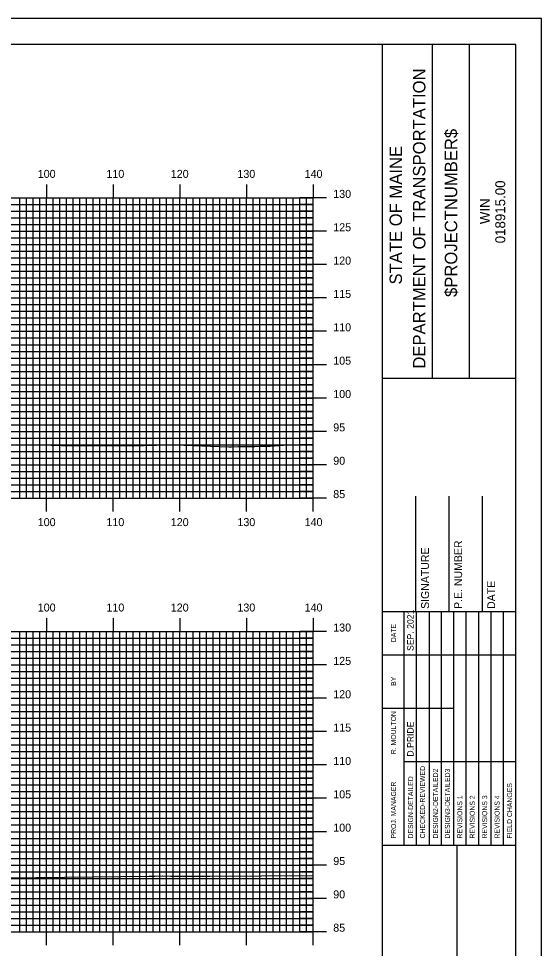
# Model space of a CAD drawing. Extents: x 1785795 to 1786139, y 442591 to 442811.
# Drawn here: x 1786056.9 to 1786135.3, y 442671.2 to 442810.5 of the extents above; entities that cross this region are included whole.
import ezdxf

# ---------------------------------------------------------------- set-up
doc = ezdxf.new("R2010")
doc.units = 0
for name, color, linetype in [('BORDER', 7, 'Continuous'), ('H_V ANNOTATION', 7, 'Continuous'), ('MAJOR', 7, 'Continuous'), ('MINOR', 7, 'Continuous'), ('PLOT BOUNDARY', 7, 'Continuous'), ('S_Roadway_Centerline', 7, 'Continuous')]:
    doc.layers.add(name, color=color, linetype=linetype)

msp = doc.modelspace()

# ---------------------------------------------------------------- linework, layer by layer
at = {"layer": 'BORDER'}
for p, q in [((1786111.45, 442596.67), (1786111.45, 442806.67)), ((1786118.91, 442756.66), (1786118.91, 442806.66)), ((1786124.5, 442756.66), (1786124.5, 442806.66)), ((1786111.45, 442756.65), (1786131.45, 442756.65)), ((1786116.45, 442721.67), (1786116.45, 442738.97)), ((1786121.45, 442721.67), (1786121.45, 442738.97)), ((1786126.45, 442721.67), (1786126.45, 442738.97)), ((1786111.45, 442721.67), (1786131.45, 442721.67)), ((1786111.45, 442686.67), (1786131.45, 442686.67)), ((1786122.63, 442616.67), (1786122.63, 442686.67))]:
    msp.add_line(p, q, dxfattribs=at)
msp.add_lwpolyline([(1785811.45, 442596.67), (1786131.45, 442596.67), (1786131.45, 442806.67), (1785811.45, 442806.67)], close=True, dxfattribs=at)
for points in [[(1786114.68, 442715.17), (1786114.68, 442721.67)], [(1786116.55, 442686.68), (1786116.55, 442721.67)], [(1786118.41, 442721.67), (1786118.41, 442686.68)], [(1786120.27, 442686.68), (1786120.27, 442721.67)], [(1786122.14, 442686.68), (1786122.14, 442721.67)], [(1786124, 442686.68), (1786124, 442721.67)], [(1786125.86, 442686.68), (1786125.86, 442721.67)], [(1786127.73, 442686.68), (1786127.73, 442721.67)], [(1786129.59, 442686.68), (1786129.59, 442721.67)], [(1786114.68, 442686.68), (1786114.68, 442720.26)], [(1786111.45, 442715.17), (1786131.45, 442715.17)], [(1786111.45, 442707.17), (1786114.68, 442707.17)], [(1786114.68, 442707.17), (1786122.13, 442707.17)], [(1786114.68, 442699.17), (1786131.45, 442699.17)]]:
    msp.add_lwpolyline(points, dxfattribs=at)
at = {"layer": 'MAJOR'}
for p, q in [((1786061.05, 442785.67), (1786061.05, 442783.67)), ((1786071.05, 442785.67), (1786071.05, 442783.67)), ((1786081.05, 442785.67), (1786081.05, 442783.67)), ((1786091.05, 442785.67), (1786091.05, 442783.67)), ((1786101.05, 442785.67), (1786101.05, 442783.67)), ((1785821.05, 442783.67), (1786101.05, 442783.67)), ((1785821.05, 442783.67), (1786101.05, 442783.67)), ((1786061.05, 442738.67), (1786061.05, 442783.67)), ((1786071.05, 442738.67), (1786071.05, 442783.67)), ((1786081.05, 442738.67), (1786081.05, 442783.67)), ((1786091.05, 442738.67), (1786091.05, 442783.67)), ((1786103.06, 442783.67), (1786099.05, 442783.67)), ((1786101.05, 442738.67), (1786101.05, 442783.67)), ((1786101.05, 442738.67), (1786101.05, 442783.67)), ((1785821.05, 442778.67), (1786101.05, 442778.67)), ((1786103.06, 442778.67), (1786099.05, 442778.67)), ((1785821.05, 442773.67), (1786101.05, 442773.67)), ((1786103.06, 442773.67), (1786099.05, 442773.67)), ((1785821.05, 442768.67), (1786101.05, 442768.67)), ((1786103.06, 442768.67), (1786099.05, 442768.67)), ((1785821.05, 442763.67), (1786101.05, 442763.67)), ((1786103.06, 442763.67), (1786099.05, 442763.67)), ((1785821.05, 442758.67), (1786101.05, 442758.67)), ((1786103.06, 442758.67), (1786099.05, 442758.67)), ((1785821.05, 442753.67), (1786101.05, 442753.67)), ((1786103.06, 442753.67), (1786099.05, 442753.67)), ((1785821.05, 442748.67), (1786101.05, 442748.67)), ((1786103.06, 442748.67), (1786099.05, 442748.67)), ((1785821.05, 442743.67), (1786101.05, 442743.67)), ((1786103.06, 442743.67), (1786099.05, 442743.67)), ((1785821.05, 442738.67), (1786101.05, 442738.67)), ((1785821.05, 442738.67), (1786101.05, 442738.67)), ((1786061.05, 442736.66), (1786061.05, 442738.67)), ((1786071.05, 442736.66), (1786071.05, 442738.67)), ((1786081.05, 442736.66), (1786081.05, 442738.67)), ((1786091.05, 442736.66), (1786091.05, 442738.67)), ((1786103.06, 442738.67), (1786099.05, 442738.67)), ((1786101.05, 442736.66), (1786101.05, 442738.67)), ((1786061.05, 442720.67), (1786061.05, 442718.67)), ((1786071.05, 442720.67), (1786071.05, 442718.67)), ((1786081.05, 442720.67), (1786081.05, 442718.67)), ((1786091.05, 442720.67), (1786091.05, 442718.67)), ((1786101.05, 442720.67), (1786101.05, 442718.67)), ((1785821.05, 442718.67), (1786101.05, 442718.67)), ((1785821.05, 442718.67), (1786101.05, 442718.67)), ((1786061.05, 442673.67), (1786061.05, 442718.67)), ((1786071.05, 442673.67), (1786071.05, 442718.67)), ((1786081.05, 442673.67), (1786081.05, 442718.67)), ((1786091.05, 442673.67), (1786091.05, 442718.67)), ((1786103.06, 442718.67), (1786099.05, 442718.67)), ((1786101.05, 442673.67), (1786101.05, 442718.67)), ((1786101.05, 442673.67), (1786101.05, 442718.67)), ((1785821.05, 442713.67), (1786101.05, 442713.67)), ((1786103.06, 442713.67), (1786099.05, 442713.67)), ((1785821.05, 442708.67), (1786101.05, 442708.67)), ((1786103.06, 442708.67), (1786099.05, 442708.67)), ((1785821.05, 442703.67), (1786101.05, 442703.67)), ((1786103.06, 442703.67), (1786099.05, 442703.67)), ((1785821.05, 442698.67), (1786101.05, 442698.67)), ((1786103.06, 442698.67), (1786099.05, 442698.67)), ((1785821.05, 442693.67), (1786101.05, 442693.67)), ((1786103.06, 442693.67), (1786099.05, 442693.67)), ((1785821.05, 442688.67), (1786101.05, 442688.67)), ((1786103.06, 442688.67), (1786099.05, 442688.67)), ((1785821.05, 442683.67), (1786101.05, 442683.67)), ((1786103.06, 442683.67), (1786099.05, 442683.67)), ((1785821.05, 442678.67), (1786101.05, 442678.67)), ((1786103.06, 442678.67), (1786099.05, 442678.67)), ((1785821.05, 442673.67), (1786101.05, 442673.67)), ((1785821.05, 442673.67), (1786101.05, 442673.67)), ((1786061.05, 442671.66), (1786061.05, 442673.67)), ((1786071.05, 442671.66), (1786071.05, 442673.67)), ((1786081.05, 442671.66), (1786081.05, 442673.67)), ((1786091.05, 442671.66), (1786091.05, 442673.67)), ((1786103.06, 442673.67), (1786099.05, 442673.67)), ((1786101.05, 442671.66), (1786101.05, 442673.67))]:
    msp.add_line(p, q, dxfattribs=at)
at = {"layer": 'MINOR'}
for p, q in [((1785821.05, 442782.67), (1786101.05, 442782.67)), ((1786057.05, 442738.67), (1786057.05, 442783.67)), ((1786058.05, 442738.67), (1786058.05, 442783.67)), ((1786059.05, 442738.67), (1786059.05, 442783.67)), ((1786060.05, 442738.67), (1786060.05, 442783.67)), ((1786062.05, 442738.67), (1786062.05, 442783.67)), ((1786063.05, 442738.67), (1786063.05, 442783.67)), ((1786064.05, 442738.67), (1786064.05, 442783.67)), ((1786065.05, 442738.67), (1786065.05, 442783.67)), ((1786066.05, 442738.67), (1786066.05, 442783.67)), ((1786067.05, 442738.67), (1786067.05, 442783.67)), ((1786068.05, 442738.67), (1786068.05, 442783.67)), ((1786069.05, 442738.67), (1786069.05, 442783.67)), ((1786070.05, 442738.67), (1786070.05, 442783.67)), ((1786072.05, 442738.67), (1786072.05, 442783.67)), ((1786073.05, 442738.67), (1786073.05, 442783.67)), ((1786074.05, 442738.67), (1786074.05, 442783.67)), ((1786075.05, 442738.67), (1786075.05, 442783.67)), ((1786076.05, 442738.67), (1786076.05, 442783.67)), ((1786077.05, 442738.67), (1786077.05, 442783.67)), ((1786078.05, 442738.67), (1786078.05, 442783.67)), ((1786079.05, 442738.67), (1786079.05, 442783.67)), ((1786080.05, 442738.67), (1786080.05, 442783.67)), ((1786082.05, 442738.67), (1786082.05, 442783.67)), ((1786083.05, 442738.67), (1786083.05, 442783.67)), ((1786084.05, 442738.67), (1786084.05, 442783.67)), ((1786085.05, 442738.67), (1786085.05, 442783.67)), ((1786086.05, 442738.67), (1786086.05, 442783.67)), ((1786087.05, 442738.67), (1786087.05, 442783.67)), ((1786088.05, 442738.67), (1786088.05, 442783.67)), ((1786089.05, 442738.67), (1786089.05, 442783.67)), ((1786090.05, 442738.67), (1786090.05, 442783.67)), ((1786092.05, 442738.67), (1786092.05, 442783.67)), ((1786093.05, 442738.67), (1786093.05, 442783.67)), ((1786094.05, 442738.67), (1786094.05, 442783.67)), ((1786095.05, 442738.67), (1786095.05, 442783.67)), ((1786096.05, 442738.67), (1786096.05, 442783.67)), ((1786097.05, 442738.67), (1786097.05, 442783.67)), ((1786098.05, 442738.67), (1786098.05, 442783.67)), ((1786099.05, 442738.67), (1786099.05, 442783.67)), ((1786101.05, 442782.67), (1786099.05, 442782.67)), ((1786100.05, 442738.67), (1786100.05, 442783.67)), ((1785821.05, 442781.67), (1786101.05, 442781.67)), ((1786101.05, 442781.67), (1786099.05, 442781.67)), ((1785821.05, 442780.67), (1786101.05, 442780.67)), ((1786101.05, 442780.67), (1786099.05, 442780.67)), ((1785821.05, 442779.67), (1786101.05, 442779.67)), ((1786101.05, 442779.67), (1786099.05, 442779.67)), ((1785821.05, 442777.67), (1786101.05, 442777.67)), ((1786101.05, 442777.67), (1786099.05, 442777.67)), ((1785821.05, 442776.67), (1786101.05, 442776.67)), ((1785821.05, 442775.67), (1786101.05, 442775.67)), ((1786101.05, 442776.67), (1786099.05, 442776.67)), ((1786101.05, 442775.67), (1786099.05, 442775.67)), ((1785821.05, 442774.67), (1786101.05, 442774.67)), ((1786101.05, 442774.67), (1786099.05, 442774.67)), ((1785821.05, 442772.67), (1786101.05, 442772.67)), ((1785821.05, 442771.67), (1786101.05, 442771.67)), ((1786101.05, 442772.67), (1786099.05, 442772.67)), ((1786101.05, 442771.67), (1786099.05, 442771.67)), ((1785821.05, 442770.67), (1786101.05, 442770.67)), ((1786101.05, 442770.67), (1786099.05, 442770.67)), ((1785821.05, 442769.67), (1786101.05, 442769.67)), ((1786101.05, 442769.67), (1786099.05, 442769.67)), ((1785821.05, 442767.67), (1786101.05, 442767.67)), ((1786101.05, 442767.67), (1786099.05, 442767.67)), ((1785821.05, 442766.67), (1786101.05, 442766.67)), ((1786101.05, 442766.67), (1786099.05, 442766.67)), ((1785821.05, 442765.67), (1786101.05, 442765.67)), ((1785821.05, 442764.67), (1786101.05, 442764.67)), ((1786101.05, 442765.67), (1786099.05, 442765.67)), ((1786101.05, 442764.67), (1786099.05, 442764.67)), ((1785821.05, 442762.67), (1786101.05, 442762.67)), ((1785821.05, 442761.67), (1786101.05, 442761.67)), ((1786101.05, 442762.67), (1786099.05, 442762.67)), ((1786101.05, 442761.67), (1786099.05, 442761.67)), ((1785821.05, 442760.67), (1786101.05, 442760.67)), ((1786101.05, 442760.67), (1786099.05, 442760.67)), ((1785821.05, 442759.67), (1786101.05, 442759.67)), ((1786101.05, 442759.67), (1786099.05, 442759.67)), ((1785821.05, 442757.67), (1786101.05, 442757.67)), ((1786101.05, 442757.67), (1786099.05, 442757.67)), ((1785821.05, 442756.67), (1786101.05, 442756.67)), ((1786101.05, 442756.67), (1786099.05, 442756.67)), ((1785821.05, 442755.67), (1786101.05, 442755.67)), ((1785821.05, 442754.67), (1786101.05, 442754.67)), ((1786101.05, 442755.67), (1786099.05, 442755.67)), ((1786101.05, 442754.67), (1786099.05, 442754.67)), ((1785821.05, 442752.67), (1786101.05, 442752.67)), ((1786101.05, 442752.67), (1786099.05, 442752.67)), ((1785821.05, 442751.67), (1786101.05, 442751.67)), ((1785821.05, 442750.67), (1786101.05, 442750.67)), ((1786101.05, 442751.67), (1786099.05, 442751.67)), ((1786101.05, 442750.67), (1786099.05, 442750.67)), ((1785821.05, 442749.67), (1786101.05, 442749.67)), ((1786101.05, 442749.67), (1786099.05, 442749.67)), ((1785821.05, 442747.67), (1786101.05, 442747.67)), ((1786101.05, 442747.67), (1786099.05, 442747.67)), ((1785821.05, 442746.67), (1786101.05, 442746.67)), ((1786101.05, 442746.67), (1786099.05, 442746.67)), ((1785821.05, 442745.67), (1786101.05, 442745.67)), ((1786101.05, 442745.67), (1786099.05, 442745.67)), ((1785821.05, 442744.67), (1786101.05, 442744.67)), ((1786101.05, 442744.67), (1786099.05, 442744.67)), ((1785821.05, 442742.67), (1786101.05, 442742.67)), ((1786101.05, 442742.67), (1786099.05, 442742.67)), ((1785821.05, 442741.67), (1786101.05, 442741.67)), ((1786101.05, 442741.67), (1786099.05, 442741.67)), ((1785821.05, 442740.67), (1786101.05, 442740.67)), ((1785821.05, 442739.67), (1786101.05, 442739.67)), ((1786101.05, 442740.67), (1786099.05, 442740.67)), ((1786101.05, 442739.67), (1786099.05, 442739.67)), ((1786057.05, 442673.67), (1786057.05, 442718.67)), ((1786058.05, 442673.67), (1786058.05, 442718.67)), ((1786059.05, 442673.67), (1786059.05, 442718.67)), ((1786060.05, 442673.67), (1786060.05, 442718.67)), ((1786062.05, 442673.67), (1786062.05, 442718.67)), ((1786063.05, 442673.67), (1786063.05, 442718.67)), ((1786064.05, 442673.67), (1786064.05, 442718.67)), ((1786065.05, 442673.67), (1786065.05, 442718.67)), ((1786066.05, 442673.67), (1786066.05, 442718.67)), ((1786067.05, 442673.67), (1786067.05, 442718.67)), ((1786068.05, 442673.67), (1786068.05, 442718.67)), ((1786069.05, 442673.67), (1786069.05, 442718.67)), ((1786070.05, 442673.67), (1786070.05, 442718.67)), ((1786072.05, 442673.67), (1786072.05, 442718.67)), ((1786073.05, 442673.67), (1786073.05, 442718.67)), ((1786074.05, 442673.67), (1786074.05, 442718.67)), ((1786075.05, 442673.67), (1786075.05, 442718.67)), ((1786076.05, 442673.67), (1786076.05, 442718.67)), ((1786077.05, 442673.67), (1786077.05, 442718.67)), ((1786078.05, 442673.67), (1786078.05, 442718.67)), ((1786079.05, 442673.67), (1786079.05, 442718.67)), ((1786080.05, 442673.67), (1786080.05, 442718.67)), ((1786082.05, 442673.67), (1786082.05, 442718.67)), ((1786083.05, 442673.67), (1786083.05, 442718.67)), ((1786084.05, 442673.67), (1786084.05, 442718.67)), ((1786085.05, 442673.67), (1786085.05, 442718.67)), ((1786086.05, 442673.67), (1786086.05, 442718.67)), ((1786087.05, 442673.67), (1786087.05, 442718.67)), ((1786088.05, 442673.67), (1786088.05, 442718.67)), ((1786089.05, 442673.67), (1786089.05, 442718.67)), ((1786090.05, 442673.67), (1786090.05, 442718.67)), ((1786092.05, 442673.67), (1786092.05, 442718.67)), ((1786093.05, 442673.67), (1786093.05, 442718.67)), ((1786094.05, 442673.67), (1786094.05, 442718.67)), ((1786095.05, 442673.67), (1786095.05, 442718.67)), ((1786096.05, 442673.67), (1786096.05, 442718.67)), ((1786097.05, 442673.67), (1786097.05, 442718.67)), ((1786098.05, 442673.67), (1786098.05, 442718.67)), ((1786099.05, 442673.67), (1786099.05, 442718.67)), ((1786100.05, 442673.67), (1786100.05, 442718.67)), ((1785821.05, 442717.67), (1786101.05, 442717.67)), ((1786101.05, 442717.67), (1786099.05, 442717.67)), ((1785821.05, 442716.67), (1786101.05, 442716.67)), ((1785821.05, 442715.67), (1786101.05, 442715.67)), ((1786101.05, 442716.67), (1786099.05, 442716.67)), ((1786101.05, 442715.67), (1786099.05, 442715.67)), ((1785821.05, 442714.67), (1786101.05, 442714.67)), ((1786101.05, 442714.67), (1786099.05, 442714.67)), ((1785821.05, 442712.67), (1786101.05, 442712.67)), ((1785821.05, 442711.67), (1786101.05, 442711.67)), ((1786101.05, 442712.67), (1786099.05, 442712.67)), ((1786101.05, 442711.67), (1786099.05, 442711.67)), ((1785821.05, 442710.67), (1786101.05, 442710.67)), ((1786101.05, 442710.67), (1786099.05, 442710.67)), ((1785821.05, 442709.67), (1786101.05, 442709.67)), ((1786101.05, 442709.67), (1786099.05, 442709.67)), ((1785821.05, 442707.67), (1786101.05, 442707.67)), ((1786101.05, 442707.67), (1786099.05, 442707.67)), ((1785821.05, 442706.67), (1786101.05, 442706.67)), ((1786101.05, 442706.67), (1786099.05, 442706.67)), ((1785821.05, 442705.67), (1786101.05, 442705.67)), ((1785821.05, 442704.67), (1786101.05, 442704.67)), ((1786101.05, 442705.67), (1786099.05, 442705.67)), ((1786101.05, 442704.67), (1786099.05, 442704.67)), ((1785821.05, 442702.67), (1786101.05, 442702.67)), ((1785821.05, 442701.67), (1786101.05, 442701.67)), ((1786101.05, 442702.67), (1786099.05, 442702.67)), ((1786101.05, 442701.67), (1786099.05, 442701.67)), ((1785821.05, 442700.67), (1786101.05, 442700.67)), ((1786101.05, 442700.67), (1786099.05, 442700.67)), ((1785821.05, 442699.67), (1786101.05, 442699.67)), ((1786101.05, 442699.67), (1786099.05, 442699.67)), ((1785821.05, 442697.67), (1786101.05, 442697.67)), ((1786101.05, 442697.67), (1786099.05, 442697.67)), ((1785821.05, 442696.67), (1786101.05, 442696.67)), ((1786101.05, 442696.67), (1786099.05, 442696.67)), ((1785821.05, 442695.67), (1786101.05, 442695.67)), ((1786101.05, 442695.67), (1786099.05, 442695.67)), ((1785821.05, 442694.67), (1786101.05, 442694.67)), ((1786101.05, 442694.67), (1786099.05, 442694.67)), ((1785821.05, 442692.67), (1786101.05, 442692.67)), ((1786101.05, 442692.67), (1786099.05, 442692.67)), ((1785821.05, 442691.67), (1786101.05, 442691.67)), ((1785821.05, 442690.67), (1786101.05, 442690.67)), ((1786101.05, 442691.67), (1786099.05, 442691.67)), ((1786101.05, 442690.67), (1786099.05, 442690.67)), ((1785821.05, 442689.67), (1786101.05, 442689.67)), ((1786101.05, 442689.67), (1786099.05, 442689.67)), ((1785821.05, 442687.67), (1786101.05, 442687.67)), ((1785821.05, 442686.67), (1786101.05, 442686.67)), ((1786101.05, 442687.67), (1786099.05, 442687.67)), ((1786101.05, 442686.67), (1786099.05, 442686.67)), ((1785821.05, 442685.67), (1786101.05, 442685.67)), ((1786101.05, 442685.67), (1786099.05, 442685.67)), ((1785821.05, 442684.67), (1786101.05, 442684.67)), ((1786101.05, 442684.67), (1786099.05, 442684.67)), ((1785821.05, 442682.67), (1786101.05, 442682.67)), ((1786101.05, 442682.67), (1786099.05, 442682.67)), ((1785821.05, 442681.67), (1786101.05, 442681.67)), ((1786101.05, 442681.67), (1786099.05, 442681.67)), ((1785821.05, 442680.67), (1786101.05, 442680.67)), ((1785821.05, 442679.67), (1786101.05, 442679.67)), ((1786101.05, 442680.67), (1786099.05, 442680.67)), ((1786101.05, 442679.67), (1786099.05, 442679.67)), ((1785821.05, 442677.67), (1786101.05, 442677.67)), ((1785821.05, 442676.67), (1786101.05, 442676.67)), ((1786101.05, 442677.67), (1786099.05, 442677.67)), ((1786101.05, 442676.67), (1786099.05, 442676.67)), ((1785821.05, 442675.67), (1786101.05, 442675.67)), ((1786101.05, 442675.67), (1786099.05, 442675.67)), ((1785821.05, 442674.67), (1786101.05, 442674.67)), ((1786101.05, 442674.67), (1786099.05, 442674.67))]:
    msp.add_line(p, q, dxfattribs=at)
at = {"layer": 'PLOT BOUNDARY'}
msp.add_lwpolyline([(1785795.27, 442590.55), (1786135.27, 442590.55), (1786135.27, 442810.55), (1785795.27, 442810.55)], close=True, dxfattribs=at)
at = {"layer": 'S_Roadway_Centerline'}
for points in [[(1786056.62, 442746.7), (1786061.74, 442746.62), (1786062.58, 442746.59), (1786063.29, 442746.57), (1786063.83, 442746.56), (1786065.2, 442746.55), (1786066.05, 442746.56), (1786066.5, 442746.56), (1786066.94, 442746.57), (1786067.36, 442746.57), (1786067.72, 442746.57), (1786068.03, 442746.58), (1786069.03, 442746.58), (1786069.39, 442746.58), (1786073.88, 442746.52), (1786079.37, 442746.66), (1786079.37, 442746.66), (1786079.38, 442746.66), (1786079.39, 442746.66), (1786079.4, 442746.66), (1786079.42, 442746.66), (1786079.43, 442746.66), (1786079.45, 442746.66), (1786079.47, 442746.66), (1786079.52, 442746.66), (1786079.56, 442746.66), (1786079.59, 442746.66), (1786079.63, 442746.66), (1786079.64, 442746.66), (1786079.67, 442746.66), (1786079.71, 442746.66), (1786079.73, 442746.66), (1786079.75, 442746.66), (1786079.77, 442746.66), (1786079.79, 442746.66), (1786079.81, 442746.65), (1786079.85, 442746.65), (1786079.95, 442746.65), (1786080.01, 442746.65), (1786080.08, 442746.65), (1786080.17, 442746.64), (1786080.29, 442746.64), (1786088.37, 442746.38), (1786088.55, 442746.37), (1786088.56, 442746.37), (1786088.59, 442746.37), (1786088.81, 442746.37), (1786089.79, 442746.39), (1786090.7, 442746.4), (1786091.54, 442746.42), (1786092.31, 442746.43), (1786092.99, 442746.45), (1786094.12, 442746.47), (1786094.58, 442746.48), (1786097.96, 442746.69), (1786101.05, 442746.65)], [(1786054.76, 442681.74), (1786059.54, 442681.8), (1786076.42, 442682.02), (1786077.3, 442682.02), (1786078.44, 442682.03), (1786079.71, 442681.98), (1786085.53, 442681.98), (1786101.05, 442682.1)]]:
    msp.add_lwpolyline(points, dxfattribs=at)

# ---------------------------------------------------------------- texts
at = {"layer": 'BORDER'}
for s, height, p in [('DEPARTMENT OF TRANSPORTATION', 1.8635, (1786117.87, 442758.08)), ('$PROJECTNUMBER$', 1.8635, (1786122.64, 442768.82)), ('STATE OF MAINE', 1.8635, (1786114.36, 442770.69)), ('018915.00', 1.491, (1786129.84, 442776.86)), ('WIN', 1.491, (1786127.53, 442779.73)), ('SIGNATURE', 1.181, (1786118.41, 442722.06)), ('P.E. NUMBER', 1.1811, (1786123.37, 442722.06)), ('DATE', 1.181, (1786128.33, 442722.06)), ('SEP. 2021', 0.969, (1786116.1, 442715.76)), ('DATE', 0.743, (1786113.46, 442717.08)), ('BY', 0.743, (1786113.46, 442710.54)), ('R. MOULTON', 0.745, (1786113.46, 442700.28)), ('D.PRIDE', 0.969, (1786116.1, 442699.92)), ('CHECKED-REVIEWED', 0.7455, (1786117.81, 442687.65)), ('DESIGN2-DETAILED2', 0.7455, (1786119.75, 442687.65)), ('DESIGN3-DETAILED3', 0.7455, (1786121.54, 442687.65)), ('DESIGN-DETAILED', 0.7455, (1786116.02, 442687.65)), ('PROJ. MANAGER', 0.7455, (1786113.46, 442687.65)), ('FIELD CHANGES', 0.7455, (1786130.86, 442687.65)), ('REVISIONS 1', 0.7455, (1786123.4, 442687.65)), ('REVISIONS 2', 0.7455, (1786125.27, 442687.65)), ('REVISIONS 3', 0.7455, (1786127.13, 442687.65)), ('REVISIONS 4', 0.7455, (1786128.99, 442687.65))]:
    msp.add_text(s, height=height, rotation=90, dxfattribs=at).set_placement(p)
at = {"layer": 'H_V ANNOTATION'}
for s, p in [('100', (1786059.74, 442786.67)), ('110', (1786070.04, 442786.67)), ('120', (1786079.69, 442786.67)), ('130', (1786089.68, 442786.67)), ('140', (1786099.76, 442786.67)), ('130', (1786104.05, 442783.67)), ('125', (1786104.05, 442778.67)), ('120', (1786104.05, 442773.67)), ('115', (1786104.05, 442768.67)), ('110', (1786104.05, 442763.67)), ('105', (1786104.05, 442758.67)), ('100', (1786104.05, 442753.67)), ('95', (1786104.05, 442748.67)), ('90', (1786104.05, 442743.67)), ('85', (1786104.05, 442738.67)), ('100', (1786059.74, 442734.47)), ('110', (1786070.04, 442734.47)), ('120', (1786079.69, 442734.47)), ('130', (1786089.68, 442734.47)), ('140', (1786099.76, 442734.47)), ('100', (1786059.74, 442721.67)), ('110', (1786070.04, 442721.67)), ('120', (1786079.69, 442721.67)), ('130', (1786089.68, 442721.67)), ('140', (1786099.76, 442721.67)), ('130', (1786104.05, 442718.67)), ('125', (1786104.05, 442713.67)), ('120', (1786104.05, 442708.67)), ('115', (1786104.05, 442703.67)), ('110', (1786104.05, 442698.67)), ('105', (1786104.05, 442693.67)), ('100', (1786104.05, 442688.67)), ('95', (1786104.05, 442683.67)), ('90', (1786104.05, 442678.67)), ('85', (1786104.05, 442673.67))]:
    msp.add_text(s, height=1.2, dxfattribs=at).set_placement(p)

doc.saveas('drawing.dxf')
